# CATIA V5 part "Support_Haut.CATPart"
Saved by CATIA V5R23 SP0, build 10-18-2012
Part number: Support_Haut
Material "Aluminium": density 2710 kg/m3, Young's modulus 7e+10 Pa, Poisson ratio 0.346, thermal expansion 2.36e-05 1/K
Bounding box of the stored display mesh (mm): x -45 to 45, y 0 to 70, z -7.5 to 7.5
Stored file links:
  P:\eleve\Support_Haut.CATPart
  C:\Program Files\Dassault Systemes\B23\win_b64\startup\materials\French\Catalog.CATMaterial
  d:\catia_soft\intel_a\reffiles\standard\MetricThickPitch.txt
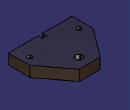
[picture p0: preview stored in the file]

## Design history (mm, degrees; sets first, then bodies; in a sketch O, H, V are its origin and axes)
Body1 (main body)
  Sketch1 on xy-plane, origin (0, 0, 0), H (1, 0, 0), V (0, 1, 0)
    point P1 (-45, 0)
    line L1 (-45, 0) -> (45, 0)
    line L2 (45, 0) -> (45, 30)
    point P3 (45, 30)
    line L3 (45, 30) -> (15, 70)
    point P4 (15, 70)
    line L4 (15, 70) -> (-15, 70)
    point P5 (-15, 70)
    line L5 (-15, 70) -> (-45, 30)
    line L6 (-45, 30) -> (-45, 0)
    reference intersected line E1 through (0, 0) direction (0, 1) from yz-plane
    reference intersected line E2 through (0, 0) direction (0, 1) from yz-plane
    reference intersected line E3 through (0, 0) direction (-1, 0) from zx-plane
    distance L6 L2 = 90
    distance E3 L4 = 70
    distance L2 P4 = 30
    distance P3 L4 = 40
    coincidence: P1 H
    horizontal: L1 H, L4 H
    vertical: L2 V, L6 V
    symmetry: L6 L2 E1, P4 P5 E2, L3 L5 V
  Pad1: profile Sketch1, direction (0, 0, 1), length 7.5, mirrored extent
  Sketch2 on face of Pad1, origin (26.3844, 19.2303, -7.5), H (1, 0, 0), V (0, -1, 0)
    point P1 (8.6156, -0.7697)
    reference intersected line E1 (-71.3844, 19.2303) -> (18.6156, 19.2303) from face of Pad1
    reference intersected line E2 through (-26.3844, 0) direction (0, 1) from yz-plane
    distance E1 P1 = 20
    distance P1 E2 = 35
  Hole1: placed by Sketch2, at (35, 20, -7.5) direction (0, 0, 1), diameter 6.5, through (limit type 3), counterbore diameter 10, counterbore depth 12
  Mirror1: of Hole1, about yz-plane
  Sketch3 "Esquisse.3" on face of Pad1, origin (-2.0176, 52.3359, -7.5), H (1, 0, 0), V (0, -1, 0)
    point P1 (2.0176, -2.6641)
    reference intersected line E1 through (2.0176, 0) direction (0, 1) from yz-plane
    reference intersected line E2 (-42.9824, 52.3359) -> (47.0176, 52.3359) from face of Pad1
    distance E2 P1 = 55
    coincidence: P1 E1
  Hole2 "Trou.2": placed by Sketch3, at (0, 55, -7.5) direction (0, 0, 1), diameter 10, through (limit type 3)
  Sketch4 "Esquisse.4" on xy-plane, origin (0, 0, 0), H (1, 0, 0), V (0, 1, 0)
    line L1 (-3, -4) -> (3, -4)
    line L2 (3, -4) -> (3, 6)
    line L3 (3, 6) -> (-3, 6)
    line L4 (-3, 6) -> (-3, -4)
    reference intersected line E1 through (0, 0) direction (0, 1) from yz-plane
    reference intersected line E2 (45, 0) -> (-45, 0) from face of Pad1
    distance L4 L2 = 6
    distance L3 E2 = 6
    distance L1 H = 4
    horizontal: L1 H, L3 H
    vertical: L2 V, L4 V
    symmetry: L4 L2 E1
  Pocket1: profile Sketch4, direction (0, 0, -1), through (limit type 3), opposite side through (limit type 3)
  Sketch5 on face of Pad1, origin (-33.8023, 0, -1.5862), H (1, 0, 0), V (0, 0, 1)
    point P1 (-1.1977, 1.5862)
    reference intersected line E1 through (0, 1.5862) direction (-1, 0) from xy-plane
    reference intersected line E2 through (33.8023, 0) direction (0, 1) from yz-plane
    distance P1 E2 = 35
    coincidence: P1 E1
  Hole3 "Trou.3": placed by Sketch5, at (-35, 0, 0) direction (0, 1, 0), diameter 4.134, depth 12, V-bottom angle 120, threaded "M5", thread diameter 5, thread depth 10, pitch 0.8
  Mirror2: of Hole3, about yz-plane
